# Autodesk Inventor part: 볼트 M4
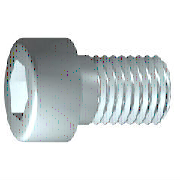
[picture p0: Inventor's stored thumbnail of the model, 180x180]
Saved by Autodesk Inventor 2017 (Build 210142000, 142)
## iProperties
IsCustomPart: 0
Created: 2012-02
Part Number: 볼트 M4
Material: 스테인리스강
Description: 6각 소켓 머리 캡 나사
Document SubType Name: Modeling
Standard: ISO 4762
Designer: mduedu
Standard Revision: Fourth edition 2004-03-01
Standards Organization: ISO
Language: ko-KR
Size Designation: M4 x 12
Categories: <MemberInstance><Categories><Category DisplayName="조임쇠" InternalName="e4da775c-781d-43d5-af7c-5136215cf5a6" Mnemonic="FSTN"><Category DisplayName="볼트" InternalN
Density: 8.08 g/cm^3
Mass: 2.29719 g
Surface Area: 3.30853 cm^2
Volume: 0.284306 cm^3
Appearance: 반광택
Author: mduedu
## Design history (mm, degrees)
sketch "스케치1"
  geometry: L1 (-1, 0)-(10, 0); L2 (10, 0)-(10, 2); L3 (10, 2)-(1.75, 2); L4 (1.75, 2)-(1.32, 2); L5 (1.32, 2)-(0, 2); L6 (0, 2)-(0, 3.5); L7 (0, 3.5)-(-4, 3.5); L8 (-4, 3.5)-(-4, 1.732); L9 (-4, 1.732)-(-2, 1.732); L10 (-2, 1.732)-(-1, 0); L11 (-7.2, 0)-(15.2, 0) reference; L12 (0, -0.7)-(0, 4.2) reference; L13 (1.75, 2)-(0, 2)
  constraints: 22 end point, 6 parallel, 2 collinear, 2 perpendicular, 1 horizontal, 1 point on line
  dimensions: "d1" = 8.25 distance from line of L3.end L2 (= GEL); "d2" = 0.42952 distance of L4.end L3.end (computed from GAL); "d3" = 4 distance between parallel lines of L8 L6 (= KOH); "d4" = 2 distance of L8.end L9.end (= INTI); "d5" = 60 deg angle of L10 L1; "d6" = 4 diameter of L3 L1 (= GD); "d7" = 4 diameter of L5 L1 (= BDM); "d8" = 3.4641 diameter of L9 L1 (= 1.1547 x SW); "d9" = 7 diameter of L7 L1 (= KOD); "d26" = 10 distance between parallel lines of L12 L2 (= NLG)
revolve "본체" sketch "스케치1" stored, may be unused: angle "d10" = 90 deg
sketch "스케치2"
  geometry: L1 (0, -4.9)-(0, 4.9) reference; L2 (-4.9, 0)-(4.9, 0) reference; L3 (1.732, 0)-(0.866, -1.5); L4 (0.866, -1.5)-(-0.866, -1.5); L5 (-0.866, -1.5)-(-1.732, 0); L6 (-1.732, 0)-(-0.866, 1.5); L7 (-0.866, 1.5)-(0.866, 1.5); L8 (0.866, 1.5)-(1.732, 0); 2 further points
  constraints: 12 end point, 1 coincident, 1 horizontal alignment, 1 point on line, 12 other
extrude "슬롯" join sketch "스케치2" stored distance "d11" = 10; taper "d12" = 0 deg
workplane "Work Plane1"
fillet "Fillet2" dims "d30" = 0.1 (= R)
body "Solid1"
fillet "모깎기1" dims "d17" = 0.4 (= RR)
feature "스레드" dims "d13" = 8.25 (= GEL), "d14" = 0
chamfer "모따기1" distance "d15" = 0.42941 (= -0.5 x SPD + 0.5 x GD); stored, may be unused: second distance "d16" = 0.42941 (= GUL), angle "d27" = 45 deg
other parameters: "GD" = 4 [user parameter; used in 2 equation terms], "NLG" = 10 [user parameter; used in 1 equation term], "GEL" = 8.25 [user parameter; used in 2 equation terms], "KOD" = 7 [user parameter; used in 1 equation term], "KOH" = 4 [user parameter; used in 1 equation term], "INTI" = 2 [user parameter; used in 1 equation term], "GAL" = 0.42941 (= 0.61345 x PTC) [user parameter; used in 1 equation term], "GUL" = 0.42941 (= 0.61345 x PTC) [user parameter; used in 1 equation term], "BDM" = 4 (= NND) [user parameter; used in 1 equation term], "SW" = 3 [user parameter; used in 2 equation terms], "RR" = 0.4 [user parameter; used in 1 equation term], "SPD" = 3.14117 (= NND - 1.2269 x PTC) [user parameter; used in 1 equation term], "d19" = 0, "d28" = 0, "d29" = 0, "R" = 0.1 [user parameter; used in 1 equation term], "TOA" = 30 deg [user parameter], "GD1" = 3.14117 (= THREADDIA - 1.2269 x PTC) [user parameter], "THREADDIA" = 4 [user parameter; used in 1 equation term], "FAWI" = 45 deg [user parameter], "TPU" = 14.28571 (computed from PTC) [user parameter], "PTC" = 0.7 [user parameter; used in 5 equation terms], "NND" = 4 [user parameter; used in 2 equation terms], "E0" = 3.465 (= 1.155 x SW) [user parameter]
